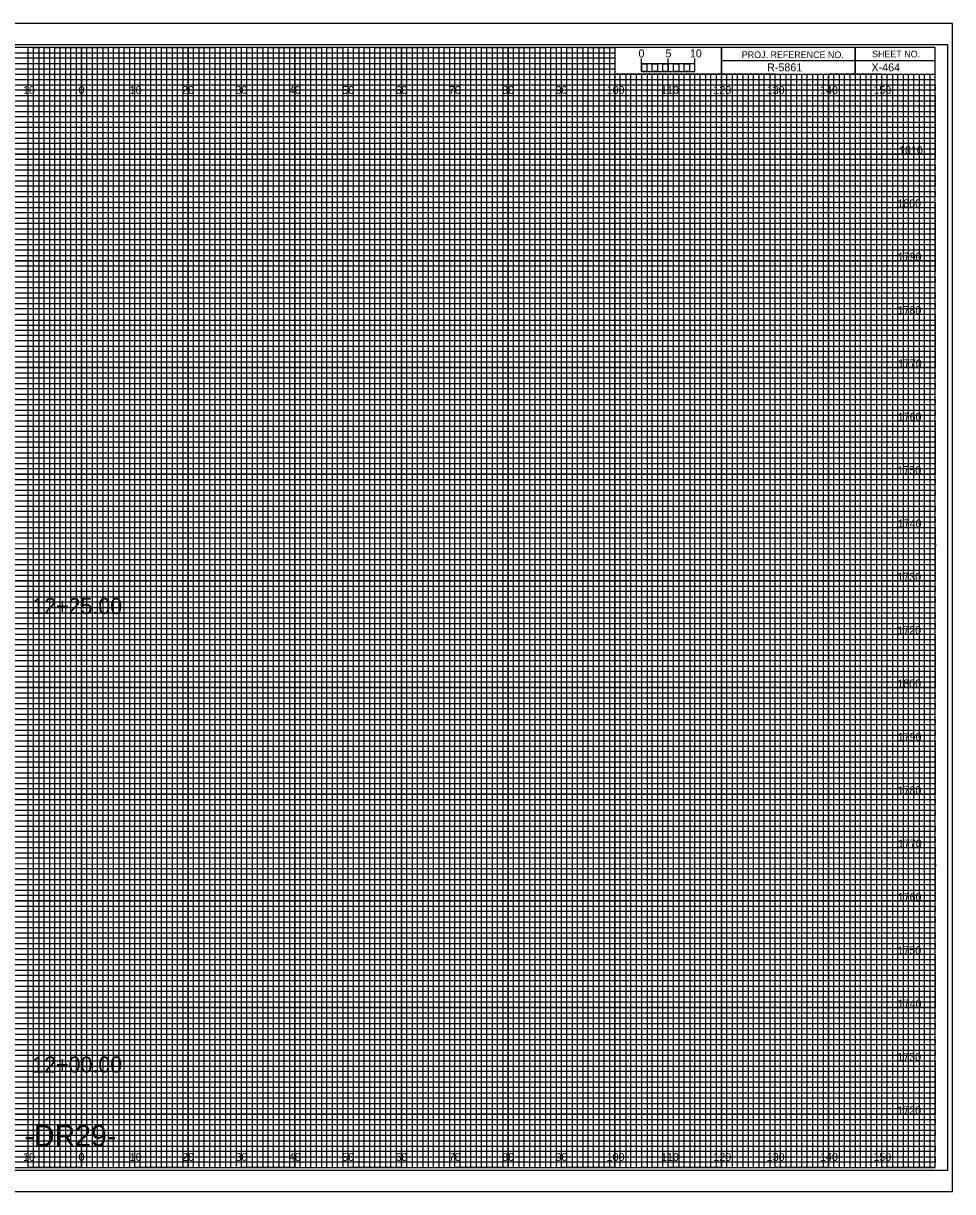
# Model space of a CAD drawing. Extents: x -13 to 323, y -5 to 874.
# Drawn here: x 149.1 to 323.3, y 655.5 to 874.5 of the extents above; entities that cross this region are included whole.
import ezdxf

# ---------------------------------------------------------------- set-up
doc = ezdxf.new("R2010")
doc.units = 0
for name, color, linetype in [('Prop Horizontal Alignment', 7, 'Continuous'), ('Prop XS Alignment Label', 7, 'Continuous'), ('Prop XS Bar Scale Labels', 7, 'Continuous'), ('Prop XS DDE', 7, 'Continuous'), ('Prop XS DDE Elevations', 7, 'Continuous'), ('Prop XS DDE Slope Text', 7, 'Continuous'), ('Prop XS Gore Control Minimum', 7, 'Continuous'), ('Prop XS Project Number', 7, 'Continuous'), ('Prop XS Sheet Number', 7, 'Continuous'), ('Prop XS Shoulder Borrow Shape', 7, 'Continuous'), ('Raster_Level_0', 7, 'Continuous'), ('Scratch_Level_3', 7, 'Continuous'), ('Sheet Cross Section Scale CELL', 7, 'Continuous'), ('Sheet Cutting Line CELL', 7, 'Continuous'), ('Sheet DOT Grid CELL', 7, 'Continuous'), ('Sheet Plot Border Inside CELL', 7, 'Continuous'), ('Sheet Plot Border Outside CELL', 7, 'Continuous')]:
    doc.layers.add(name, color=color, linetype=linetype)

msp = doc.modelspace()

# ---------------------------------------------------------------- linework, layer by layer
at = {"layer": 'Prop XS DDE'}
for p, q in [((0, 869), (260, 869)), ((260, 867.98), (0, 867.98)), ((260, 869), (260, 867.98)), ((0, 867), (260, 867)), ((260, 865.89), (0, 865.89)), ((260, 867), (260, 865.89)), ((0, 864), (320, 864))]:
    msp.add_line(p, q, dxfattribs=at)
for points in [[(0, 863), (270, 863), (320, 863), (320, 862), (0, 862)], [(0, 861), (320, 861), (320, 859), (0, 859)], [(0, 858), (320, 858), (320, 857), (0, 856.98)], [(0, 856), (320, 856), (320, 854), (0, 854)], [(0, 853), (320, 853), (320, 852), (0, 852)], [(0, 851), (320, 851), (320, 849), (0, 849)], [(0, 848), (320, 848), (320, 847), (0, 847)], [(0, 846), (320, 846), (320, 844), (0, 844)], [(0, 843), (320, 843), (320, 842), (0, 842)], [(0, 841), (320, 841), (320, 839), (0, 839)], [(0, 838), (320, 838), (320, 837), (0, 837)], [(0, 836), (320, 836), (320, 833.95), (320, 833), (320, 832), (0, 832)], [(0, 834), (320, 834), (320, 833), (0, 833)], [(0, 831), (320, 831), (320, 829), (0, 829.03)], [(0, 829.03), (320, 829), (320, 828), (0, 828)], [(0, 827), (320, 827), (320, 826), (0, 826)], [(0, 824), (320, 824), (320, 823), (0, 823)], [(0, 822), (320, 822), (320, 821), (0, 821)], [(-0.07, 818.89), (320, 818.89), (320, 817.88), (-0.07, 817.88)], [(0, 817), (320, 817), (320, 816), (0, 816)], [(0, 814), (320, 814), (320, 813), (0, 813)], [(0, 812), (320, 812), (320, 811), (0, 811)], [(0, 809), (320, 809), (320, 808), (0, 808)], [(0, 807), (320, 807), (320, 806), (0, 806)], [(0, 804), (320, 804), (320, 803), (0, 803)], [(0, 802), (320, 802), (320, 801), (0, 801)], [(0, 799), (320, 799), (319.99, 797.98), (0, 798)], [(0, 797), (320, 797), (320, 796), (0, 796)], [(0, 794), (320, 794), (320, 793), (0, 793)], [(0, 792), (320, 792), (320, 791), (0, 791)], [(0, 789), (320, 789), (320, 788), (0, 788)], [(0, 787), (320, 787), (320, 786), (0, 786)], [(0, 784), (320, 784), (320, 783), (0, 783)], [(0, 782), (320, 782), (320, 781), (0, 781)], [(0, 779), (320, 779), (320, 778), (0, 778)], [(0, 776.99), (320.07, 776.91), (320, 776), (0, 776)], [(0, 774), (320, 774), (320, 773), (0, 773)], [(0, 772), (320, 772), (320, 771), (0, 771)], [(0, 769), (320, 769), (320, 768), (0, 768)], [(0, 767), (320, 767), (320, 766), (0, 766)], [(0, 764), (320, 764), (320, 763), (0, 763)], [(0, 762), (320, 762), (320, 761), (0, 761)], [(0, 759), (320, 759), (320, 758), (0, 758)], [(0, 757), (320, 757), (320, 756), (0, 756)], [(0, 754), (320, 754), (320, 753), (0, 753)], [(0, 752), (320, 752), (320, 751), (0, 751)], [(0, 749), (320, 749), (320, 748), (0, 748)], [(0, 747), (320, 747), (320, 746), (0, 746)], [(0, 744), (320, 744), (320, 743), (0, 743)], [(0, 742), (320, 742), (320, 741), (0, 741)], [(0, 739), (320, 739), (319.99, 737.98), (0, 738)], [(0, 737), (320, 737), (320, 736), (0, 736)], [(0, 734), (320, 734), (320, 733), (0, 733)], [(0, 732), (320, 732), (320, 731), (0, 731)], [(0, 729), (320, 729), (320, 728), (0, 728)], [(0, 727), (320, 727), (320, 726), (0, 726)], [(0, 724), (320, 724), (320, 723), (0, 723)], [(0, 722), (320, 722), (320, 721), (0, 721)], [(0, 719), (320, 719), (320, 718), (0, 718)], [(0, 716.99), (320.07, 716.91), (320, 716), (0, 716)], [(0, 714), (320, 714), (320, 713), (0, 713)], [(0, 712), (320, 712), (320, 711), (0, 711)], [(0, 709), (320, 709), (320, 708), (0, 708)], [(0, 707), (320, 707), (320, 706), (0, 706)], [(0, 704), (320, 704), (320, 703), (0, 703)], [(0, 702), (320, 702), (320, 701), (0, 701)], [(0, 699), (320, 699), (320, 698), (0, 698)], [(0, 697), (320, 697), (320, 696), (0, 696)], [(0, 694), (320, 694), (320, 693), (0, 693)], [(0, 692), (320, 692), (320, 691), (0, 691)], [(0, 689), (320, 689), (320, 688), (0, 688)], [(0, 687), (320, 687), (320, 686), (0, 686)], [(0, 684), (320, 684), (320, 683), (0, 683)], [(0, 682), (320, 682), (320, 681), (0, 681)], [(0, 679), (320, 679), (320, 678), (0, 678)], [(0, 677), (320, 677), (320, 676), (0, 676)], [(0, 674), (320, 674), (320, 673), (0, 673)], [(0, 672), (320, 672), (320, 671), (0, 671)], [(0, 669), (320, 669), (320, 668), (0, 668)], [(0, 667), (320, 667), (320, 666), (0, 666)], [(0, 664), (320, 664), (320, 663), (0, 663)], [(0, 662), (320, 662), (320, 661), (0, 661)]]:
    msp.add_lwpolyline(points, dxfattribs=at)
at = {"layer": 'Prop XS DDE Elevations'}
for p, q in [((267, 865), (266.01, 865)), ((266.01, 865), (266.01, 660)), ((267, 660), (267, 865)), ((269, 865), (268, 865)), ((268, 865), (268, 660)), ((269, 660), (269, 865)), ((266.01, 660), (265, 660)), ((268, 660), (267, 660))]:
    msp.add_line(p, q, dxfattribs=at)
for points in [[(150, 660), (151, 660), (151, 870), (152, 870), (152, 660)], [(152, 660), (153, 660), (153, 870), (154, 870), (154, 660)], [(155, 660), (156, 660), (156, 870), (157, 870), (157, 660)], [(157, 660), (158, 660), (158, 870), (159, 870), (159, 660)], [(160, 660), (161, 660), (161, 870), (162, 870), (162, 660)], [(162, 660), (163, 660), (163, 870), (164, 870), (164, 660)], [(165, 660), (166, 660), (166, 870), (167, 870), (167, 660)], [(167, 660), (168, 660), (168, 870), (169, 870), (169, 660)], [(170, 660), (171, 660), (171, 870), (172, 870), (172, 660)], [(172, 660), (173, 660), (173, 870), (174, 870), (174, 660)], [(175, 660), (176, 660), (176, 870), (177, 870), (177, 660)], [(177, 660), (178, 660), (178, 870), (179, 870), (179, 660)], [(180, 660), (181, 660), (181, 870), (182, 870), (182, 660)], [(182, 660), (183, 660), (183, 870), (184, 870), (184, 660)], [(185, 660), (186, 660), (186, 870), (187, 870), (187, 660)], [(187, 660), (188, 660), (188, 870), (189, 870), (189, 660)], [(190, 660), (191, 660), (191, 870), (192, 870), (192, 660)], [(192, 660), (193, 660), (193, 870), (194, 870), (194, 660)], [(195, 660), (196, 660), (196, 870), (197, 870), (197, 660)], [(197, 660), (198, 660), (198, 870), (199, 870), (199, 660)], [(200, 660), (201, 660), (201, 870), (202, 870), (202, 660)], [(202, 660), (203, 660), (203, 870), (204, 870), (204, 660)], [(205, 660), (206, 660), (206, 870), (207, 870), (207, 660)], [(207, 660), (208, 660), (208, 870), (209, 870), (209, 660)], [(210, 660), (211, 660), (211, 870), (212, 870), (212, 660)], [(212, 660), (213, 660), (213, 870), (214, 870), (214, 660)], [(215, 660), (216, 660), (216, 870), (217, 870), (217, 660)], [(217, 660), (218, 660), (218, 870), (219, 870), (219, 660)], [(220, 660), (221, 660), (221, 870), (222, 870), (222, 660)], [(222, 660), (223, 660), (223, 870), (224, 870), (224, 660)], [(225, 660), (226, 660), (226, 870), (227, 870), (227, 660)], [(227, 660), (228, 660), (228, 870), (229, 870), (229, 660)], [(230, 660), (231, 660), (231, 870), (232, 870), (232, 660)], [(232, 660), (233, 660), (233, 870), (234, 870), (234, 660)], [(235, 660), (236, 660), (236, 870), (237, 870), (237, 660)], [(237, 660), (238, 660), (238, 870), (239, 870), (239, 660)], [(240, 660), (241, 660), (241, 870), (242, 870), (242, 660)], [(242, 660), (243, 660), (243, 870), (244, 870), (244, 660)], [(245, 660), (246, 660), (246, 870), (247, 870), (247, 660)], [(247, 660), (248, 660), (248, 870), (249, 870), (249, 660)], [(250, 660), (251, 660), (251, 870), (252, 870), (252, 660)], [(252, 660), (253, 660), (253, 870), (254, 870), (254, 660)], [(255, 660), (256, 660), (256, 870), (257, 870), (257, 660)], [(257, 660), (258, 660), (258, 870), (259, 870), (259, 660)], [(260, 660), (261, 660), (261, 865), (262.02, 865), (262.02, 660)], [(262, 660), (263, 660), (263, 865), (263.99, 865), (263.99, 660)], [(270, 660), (270.98, 660), (270.98, 865), (272, 865), (272, 660)], [(272, 660), (273, 660), (273, 865), (274.05, 865), (274.05, 660)], [(275, 660), (276, 660), (276, 865), (277, 865), (277, 660)], [(277, 660), (278, 660), (278, 865), (279, 865), (279, 660)], [(280, 660), (281, 660), (281, 865), (282, 865), (282, 660)], [(282, 660), (283, 660), (283, 865), (284, 865), (284, 660)], [(285, 660), (286, 660), (286, 865), (287, 865), (287, 660)], [(287, 660), (288, 660), (288, 865), (289, 865), (289, 660)], [(290, 660), (291, 660), (291, 865), (292, 865), (292, 660)], [(292, 660), (293, 660), (293, 865), (294, 865), (294, 660)], [(295, 660), (296, 660), (296, 865), (297, 865), (297, 660)], [(297, 660), (298, 660), (298, 865), (299, 865), (299, 660)], [(300, 660), (301, 660), (301, 865), (302, 865), (302, 660)], [(302, 660), (303, 660), (303, 865), (304, 865), (304, 660)], [(305, 660), (306, 660), (306, 865), (307, 865), (307, 660)], [(307, 660), (308, 660), (308, 865), (309, 865), (309, 660)], [(310, 660), (311, 660), (311, 865), (312, 865), (312, 660)], [(312, 660), (313, 660), (313, 865), (314, 865), (314, 660)], [(315, 660), (316, 660), (316, 865), (317, 865), (317, 660)], [(317, 660), (318, 660), (318, 865), (319, 865), (319, 660)]]:
    msp.add_lwpolyline(points, dxfattribs=at)
at = {"layer": 'Prop XS DDE Slope Text'}
for p, q in [((305, 870), (305, 865)), ((305, 865), (305, 870)), ((280, 867.5), (280, 865)), ((320, 867.49), (280, 867.49)), ((280, 865), (320, 865))]:
    msp.add_line(p, q, dxfattribs=at)
for points in [[(320, 870), (0, 870), (0, 660), (320, 660)], [(280, 870), (260, 870), (260, 865.03), (280, 865.03)], [(320, 870), (280, 870), (280, 865), (320, 865)]]:
    msp.add_lwpolyline(points, close=True, dxfattribs=at)
at = {"layer": 'Prop XS Gore Control Minimum'}
for p, q in [((150, 870), (140, 870)), ((150, 660), (150, 870)), ((170, 870), (160, 870)), ((160, 870), (160, 660)), ((170, 660), (170, 870)), ((190, 870), (180, 870)), ((180, 870), (180, 660)), ((190, 660), (190, 870)), ((210, 870), (200, 870)), ((200, 870), (200, 660)), ((210, 660), (210, 870)), ((230, 870), (220, 870)), ((220, 870), (220, 660)), ((230, 660), (230, 870)), ((250, 870), (240, 870)), ((240, 870), (240, 660)), ((250, 660), (250, 870)), ((260, 870), (260, 660)), ((270, 660), (270, 865)), ((290, 865), (280, 865)), ((280, 865), (280, 660)), ((290, 660), (290, 865)), ((310, 865), (300, 865)), ((300, 865), (300, 660)), ((310, 660), (310, 865)), ((160, 660), (150, 660)), ((180, 660), (170, 660)), ((200, 660), (190, 660)), ((220, 660), (210, 660)), ((240, 660), (230, 660)), ((260, 660), (250, 660)), ((280, 660), (270, 660)), ((300, 660), (290, 660)), ((320, 660), (310, 660)), ((320, 660), (320, 660))]:
    msp.add_line(p, q, dxfattribs=at)
for points in [[(0, 860), (320, 860), (320, 850), (0, 850)], [(0, 840), (320, 840), (320, 830), (0, 830)], [(0, 820), (320, 820), (320, 810), (0, 810)], [(0, 800), (320, 800), (320, 790), (0, 790)], [(0, 780), (320, 780), (320, 770), (0, 770)], [(0, 760), (320, 760), (320, 750), (0, 750)], [(0, 740), (320, 740), (320, 730), (0, 730)], [(0, 720), (320, 720), (320, 710), (0, 710)], [(0, 700), (320, 700), (320, 690), (0, 690)], [(0, 680), (320, 680), (320, 670), (0, 670)]]:
    msp.add_lwpolyline(points, dxfattribs=at)
at = {"layer": 'Prop XS Shoulder Borrow Shape'}
for points in [[(145, 660), (155, 660), (155, 870), (165, 870), (165, 660), (175, 660), (175, 870), (185, 870), (185, 660), (195, 660), (195, 870), (205, 870), (205, 660), (215, 660), (215, 870), (225, 870), (225, 660), (235, 660), (235, 870), (245, 870), (245, 660), (255, 660), (255, 870), (259.93, 870), (260, 870), (260, 865), (264.99, 865), (264.99, 660), (275, 660), (275, 865), (285, 865), (285, 660), (295, 660), (295, 865), (305, 865), (305, 660), (315, 660), (315, 865)], [(0, 865), (275, 865)], [(0, 845), (320, 845), (320, 855), (0, 855)], [(0, 825), (320, 825), (320, 835), (0, 835)], [(0, 805), (320, 805), (320, 815), (0, 815)], [(0, 785), (320, 785), (320, 795), (0, 795)], [(0, 765), (320, 765), (320, 775), (0, 775)], [(0, 745), (320, 745), (320, 755), (0, 755)], [(0, 725), (320, 725), (320, 735), (0, 735)], [(0, 705), (320, 705), (320, 715), (0, 715)], [(0, 685), (320, 685), (320, 695), (0, 695)], [(0, 665), (320, 665), (320, 675), (0, 675)]]:
    msp.add_lwpolyline(points, dxfattribs=at)
at = {"layer": 'Sheet Cross Section Scale CELL'}
for p, q in [((265, 865.49), (265, 867.9)), ((265, 866.9), (265, 867.9)), ((270, 865.49), (270, 867.9)), ((275, 865.49), (275, 867.9)), ((275, 866.9), (275, 867.9))]:
    msp.add_line(p, q, dxfattribs=at)
for points in [[(275, 866.9), (265, 866.9), (265, 865.49), (275, 865.49)], [(265, 866.9), (266, 866.9), (266, 865.49), (265, 865.49)], [(267, 866.9), (268, 866.9), (268, 865.49), (267, 865.49)], [(269, 866.9), (270, 866.9), (270, 865.49), (269, 865.49)], [(271, 866.9), (272, 866.9), (272, 865.49), (271, 865.49)], [(273, 866.9), (274, 866.9), (274, 865.49), (273, 865.49)]]:
    msp.add_lwpolyline(points, close=True, dxfattribs=at)
at = {"layer": 'Sheet Cutting Line CELL'}
for p, q in [((323.3, 874.5), (-13.4, 874.5)), ((-13.4, 655.5), (323.3, 655.5))]:
    msp.add_line(p, q, dxfattribs=at)
at = {"layer": 'Sheet DOT Grid CELL'}
for p, q in [((150, 660), (150, 870)), ((160, 660), (160, 870)), ((170, 660), (170, 870)), ((180, 660), (180, 870)), ((190, 660), (190, 870)), ((200, 660), (200, 870)), ((210, 660), (210, 870)), ((220, 660), (220, 870)), ((230, 660), (230, 870)), ((240, 660), (240, 870)), ((250, 660), (250, 870)), ((260, 660), (260, 864.69)), ((270, 660), (270, 864.69)), ((280, 660), (280, 864.69)), ((290, 660), (290, 864.69)), ((300, 660), (300, 864.69)), ((310, 660), (310, 864.69)), ((0, 860), (320, 860)), ((0, 850), (320, 850)), ((0, 840), (320, 840)), ((0, 830), (320, 830)), ((0, 820), (320, 820)), ((0, 810), (320, 810)), ((0, 800), (320, 800)), ((0, 790), (320, 790)), ((0, 780), (320, 780)), ((0, 770), (320, 770)), ((0, 760), (320, 760)), ((0, 750), (320, 750)), ((0, 740), (320, 740)), ((0, 730), (320, 730)), ((0, 720), (320, 720)), ((0, 710), (320, 710)), ((0, 700), (320, 700)), ((0, 690), (320, 690)), ((0, 680), (320, 680)), ((0, 670), (320, 670))]:
    msp.add_line(p, q, dxfattribs=at)
at = {"layer": 'Sheet Plot Border Inside CELL'}
msp.add_lwpolyline([(-10.8, 659.5), (322.4, 659.5), (322.4, 870.5), (-10.8, 870.5)], close=True, dxfattribs=at)
at = {"layer": 'Sheet Plot Border Outside CELL'}
msp.add_lwpolyline([(-13.4, 655.5), (323.3, 655.5), (323.3, 874.5), (-13.4, 874.5)], close=True, dxfattribs=at)

# ---------------------------------------------------------------- texts
at = {"layer": 'Prop Horizontal Alignment'}
for s, p in [('12+25.00', (150.77, 763.77)), ('12+00.00', (150.77, 677.82))]:
    msp.add_text(s, height=3, dxfattribs=at).set_placement(p)
at = {"layer": 'Prop XS Alignment Label'}
msp.add_text('-DR29-', height=4, dxfattribs=at).set_placement((149.3, 664))
at = {"layer": 'Prop XS Bar Scale Labels'}
for s, p in [('5', (269.47, 868.12)), ('10', (274.04, 868.12))]:
    msp.add_text(s, height=1.5, dxfattribs=at).set_placement(p)
at = {"layer": 'Prop XS DDE Slope Text'}
for s, p in [('PROJ. REFERENCE NO.', (283.77, 867.99)), ('SHEET NO.', (308.19, 868.12))]:
    msp.add_text(s, height=1.25, dxfattribs=at).set_placement(p)
at = {"layer": 'Prop XS Project Number'}
msp.add_text('R-5861', height=1.5, dxfattribs=at).set_placement((288.53, 865.5))
at = {"layer": 'Prop XS Sheet Number'}
msp.add_text('X-464', height=1.5, dxfattribs=at).set_placement((308.09, 865.5))
at = {"layer": 'Raster_Level_0'}
for s, p in [('10', (149.04, 861.25)), ('0', (159.45, 861.25)), ('0', (159.45, 861.25)), ('10', (169.04, 861.25)), ('20', (178.86, 861.25)), ('30', (188.86, 861.25)), ('40', (198.86, 861.25)), ('50', (208.86, 861.25)), ('60', (218.86, 861.25)), ('70', (228.86, 861.25)), ('80', (238.86, 861.25)), ('90', (248.86, 861.25)), ('100', (258.44, 861.25)), ('110', (268.62, 861.25)), ('120', (278.44, 861.25)), ('130', (288.44, 861.25)), ('140', (298.44, 861.25)), ('150', (308.44, 861.25)), ('10', (149.04, 661.25)), ('0', (159.45, 661.25)), ('0', (159.45, 661.25)), ('10', (169.04, 661.25)), ('20', (178.86, 661.25)), ('30', (188.86, 661.25)), ('40', (198.86, 661.25)), ('50', (208.86, 661.25)), ('60', (218.86, 661.25)), ('70', (228.86, 661.25)), ('80', (238.86, 661.25)), ('90', (248.86, 661.25)), ('100', (258.44, 661.25)), ('110', (268.62, 661.25)), ('120', (278.44, 661.25)), ('130', (288.44, 661.25)), ('140', (298.44, 661.25)), ('150', (308.44, 661.25))]:
    msp.add_text(s, height=1.5, dxfattribs=at).set_placement(p)
at = {"layer": 'Scratch_Level_3'}
for s, p in [('1810', (313.25, 850)), ('1800', (312.92, 840)), ('1790', (313, 830)), ('1780', (312.98, 820)), ('1770', (313.04, 810)), ('1760', (313, 800)), ('1750', (312.96, 790)), ('1740', (313, 780)), ('1730', (312.92, 770)), ('1720', (312.93, 760)), ('1800', (312.92, 750)), ('1790', (313, 740)), ('1780', (312.98, 730)), ('1770', (313.04, 720)), ('1760', (313, 710)), ('1750', (312.96, 700)), ('1740', (313, 690)), ('1730', (312.92, 680)), ('1720', (312.93, 670))]:
    msp.add_text(s, height=1.5, dxfattribs=at).set_placement(p)
at = {"layer": 'Sheet Cross Section Scale CELL'}
msp.add_text('0', height=1.5, dxfattribs=at).set_placement((264.41, 868.12))

doc.saveas('drawing.dxf')
